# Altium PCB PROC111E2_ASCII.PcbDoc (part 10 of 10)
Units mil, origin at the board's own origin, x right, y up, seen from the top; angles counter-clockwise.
Board outline 7700 x 2300 mil, 6 copper layers (Top Layer, GND 1, SIG 1, SIG 2, GND 2, Bottom Layer), stack 78.711 mil thick; 767 components, 596 nets, 2755 pads, 1578 vias.
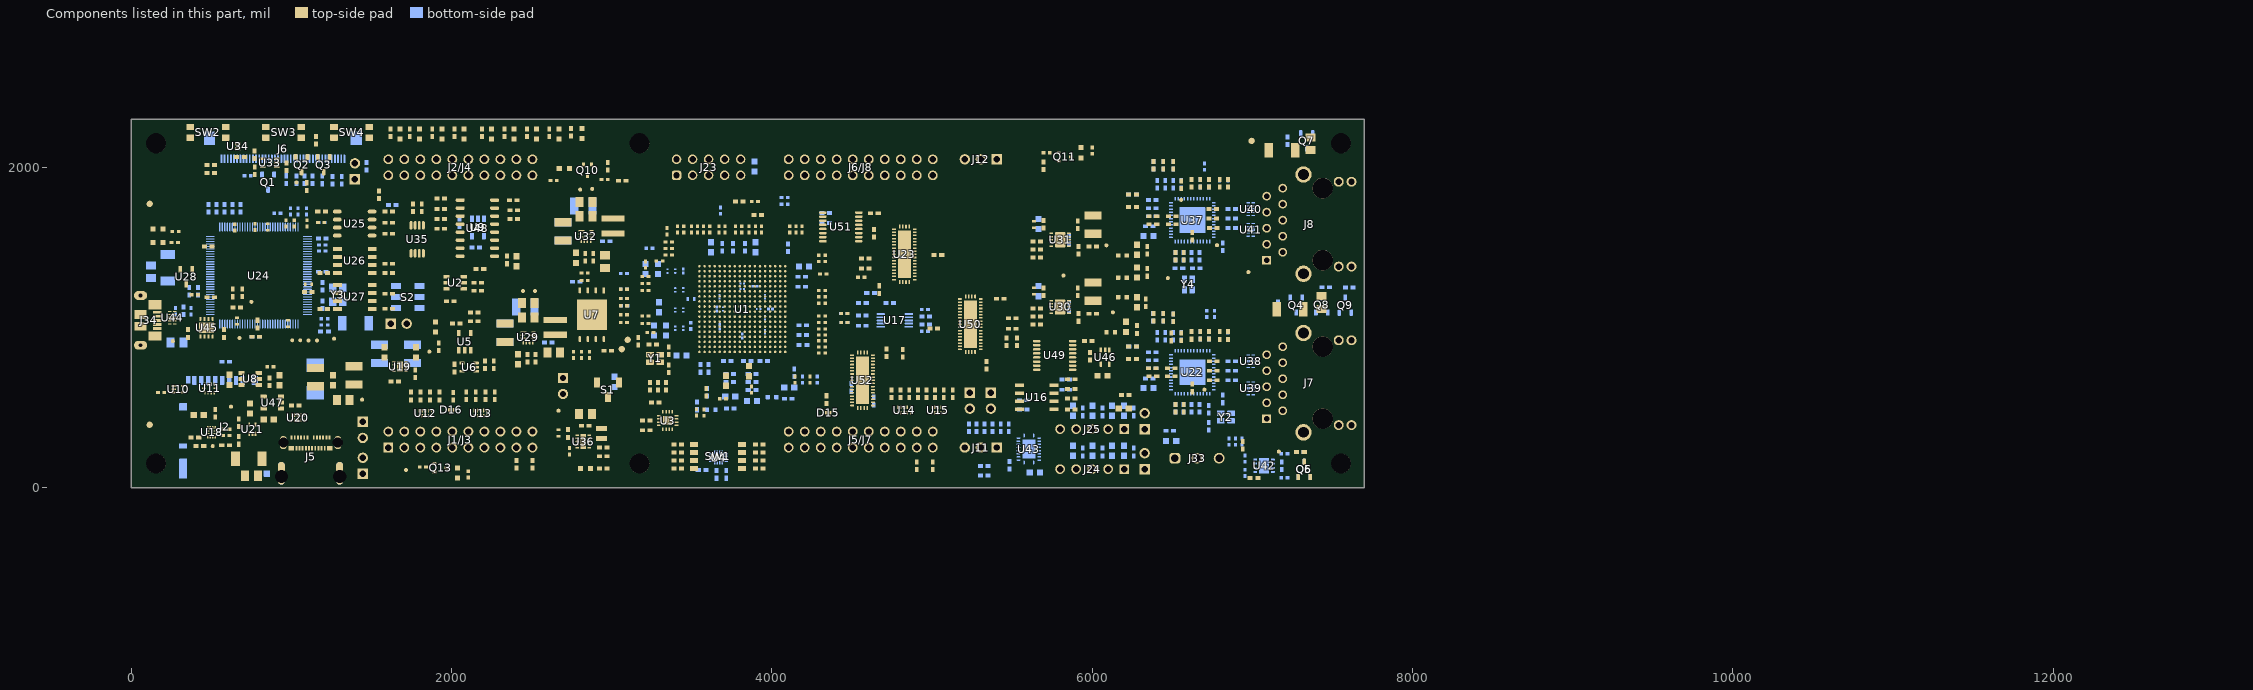
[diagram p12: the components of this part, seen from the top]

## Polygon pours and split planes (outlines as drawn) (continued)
VSYS_5V0 on SIG 2 "SIG 1-VSYS_5V0" (solid, remove dead copper, pour order 170): 5885,665 5925,625 6213.46,625 6258.42,580.04 6570.88,267.59 7230,267.55 7230,111.05 7183.95,65 2730.4,65 2569.6,199 1375,199 1375,530 1795,530 1795,919.76 1905,919.76 1905,1660 2821.22,1660 2821.22,1379.42 2494.42,1379.42 2450,1335 2450,722.59 2587.59,585 4815,585 4953.13,445 5268.44,445 5300,476.56 5300,660 5560,660 5560,1020.29 5485,1097.02 5485,1629.65 5515.35,1660 5560,1660 5885,1660
VDD_AM263_1V2 on SIG 2 "SIG 1-VDD_AM263_1V2" (solid, pour order 168): 3470.04,985 3505.4,1020.59 3625.87,1020.59 3647.25,999.21 3647.25,940.31 3615,908.06 3615,844.23 3985,844.23 3985,1070.33 4050,1070.33 4050,1155 3999.19,1155 3990,1164.19 3990,1223.39 3967.26,1246.14 3935.76,1246.14 3866.9,1315 3799.81,1315 3757.37,1272.56 3661.94,1272.56 3599.54,1334.96 2490,1334.96 2490,730.04 2706.09,730.04 2706.09,985 3106.05,985
VDD_ETH2_1V1_FILT on SIG 2 "SIG 2-VDD_ETH2_1V1_FILT" (solid, pour order 12): 6415.73,1433.78 6430.29,1448.34 6430.29,1494.41 6399.19,1525 6399.19,1671.12 6457.21,1671.12 6479.99,1648.34 6823.81,1648.34 6846.59,1671.12 6846.59,1759.22 6825.81,1780 6779.49,1780 6625.24,1934.26 6353.19,1934.26 6259.18,1840.24 6259.18,1473.95 6299.35,1433.78
VDD_ETH1_1V1_FILT on SIG 2 "SIG 2-VDD_ETH1_1V1_FILT" (solid, pour order 84): 6338.15,1339.91 6473.52,1339.91 6875.84,1339.91 6955,1260.74 6955,780.4 6863.7,689.1 6745,689.1 6713.73,720.37 6422.06,720.37 6422.06,937.27 6672.54,937.27 6798.75,937.27 6823.81,962.33 6823.81,1132.01 6751.99,1203.83 6338.15,1203.83
VSD_3V3 on SIG 2 "SIG 2-VSD_3V3" (solid, pour order 160): 510,810 631.97,810 631.97,567.83 220,567.83 220,751.21 510,751.21
SHIELD2 on SIG 2 "Top Layer-SHIELD2" (solid, pour order 211): 7250,329.68 7306.81,272.87 7412.87,272.87 7505,365 7505,416.54 7528.25,439.79 7650,439.79 7650,853.43 7535,853.43 7470,918.43 7470,1140 7250,1140
SHIELD3 on SIG 2 "Top Layer-SHIELD3" (solid, pour order 209): 7233.03,2130 7210,2106.97 7210,1963.31 7250,1923.31 7250,1277.87 7265,1262.87 7427.87,1262.87 7505,1340 7505,1406.54 7528.25,1429.79 7650,1429.79 7650,1843.43 7535,1843.43 7470,1908.43 7470,2130
VDDS_AM263_LDO_1V8 on SIG 2 "SIG 2-VDDS_AM263_LDO_1V8" (solid, pour order 14): 4144.81,1277.63 4076.04,1277.63 4061.86,1291.81 3993.63,1291.81 3993.63,1253.31 4057.7,1253.31 4091.01,1220 4140.09,1220 4154.85,1234.76 4154.85,1267.72 4143.94,1278.63
VDDS_AM263_LDO_1V8 on SIG 2 "SIG 2-VDDS_AM263_LDO_1V8 1" (solid, pour order 16): 3710,1305.1 3710,1416.01 3713.99,1420 3713.99,1460.97 3705,1469.95 3672.32,1469.95 3657.37,1455 3657.37,1415.8 3630.74,1389.17 3630.74,1315.74 3651.48,1295 3699.9,1295
GND on GND 1 "GND 1-GND" (solid, remove dead copper, pour order 200): 7504.17,284.98 7637.99,284.98 7670,317 7670,351.16 7657.89,363.27 7586.36,363.27 7569.87,379.77 7569.87,408.86 7560.02,418.7 7535,418.7 7510,393.7 7510,348.99 7406.01,245 7319,245 7315.63,244.67 7225,335.3 7225,1130 7250,1155 7476.02,1155 7588.78,1042.24 7637.99,1042.24 7637.99,1207.01 7582.13,1262.87 7250.44,1262.87 7225,1288.31 7225,2100 7270,2145 7350,2145 7385,2180 7385,2255 7365.49,2274.51 7225,2274.51 295,2275 295,1916.06 800,1916.06 800,1842.84 1445,1842.84 1445,820 498.97,820 498.97,729.88 85,729.88 85,25 7392.67,25 7415,47.33 7415,195.81
GND_XDS on GND 1 "SIG 1-VDD_XDS3V3" (solid, pour order 150): 280.17,1285.5 180,1185.32 180,1159.28 180,840 415,840 415,915 1355,915 1355,1745 695,1745 695,1830 60,1830 60,1365 280.17,1365
SHIELD1 on GND 1 "Top Layer-SHIELD1" (solid, pour order 148): 970,333.27 970,173.86 1268.3,173.86 1268.3,333.27 1335,333.27 1335,14.25 760,14.25 760,94.25 779.9,114.15 779.9,213.5 881.02,213.5 881.02,333.27
SHIELD3 on GND 1 "Top Layer-SHIELD3" (solid, pour order 235): 7233.03,2130 7210,2106.97 7210,1963.31 7250,1923.31 7250,1277.87 7265,1262.87 7427.87,1262.87 7505,1340 7505,1406.54 7528.25,1429.79 7650,1429.79 7650,1843.43 7535,1843.43 7470,1908.43 7470,2130
SHIELD2 on GND 1 "Top Layer-SHIELD2" (solid, pour order 203): 7250,329.68 7306.81,272.87 7412.87,272.87 7505,365 7505,416.54 7528.25,439.79 7650,439.79 7650,853.43 7535,853.43 7470,918.43 7470,1140 7250,1140
SHIELD4 on GND 1 "Bottom Layer-SHIELD4" (solid, pour order 158): 15,850 170,850 170,1189.07 270,1289.07 270,1333.26 15,1333.26
SHIELD1 on SIG 1 "Top Layer-SHIELD1" (solid, pour order 237): 970,333.27 970,173.86 1268.3,173.86 1268.3,333.27 1335,333.27 1335,14.25 760,14.25 760,94.25 779.9,114.15 779.9,213.5 881.02,213.5 881.02,333.27
VDDA_AM263_1V8_LDO on SIG 1 "SIG 1-VDDA_AM263_1V8_LDO" (solid, pour order 217): 3935.25,905 3975.05,905 3980.05,900 3980.05,890.84 4017.51,853.38 4017.51,767.97 4075,710.49 4123.94,710.49 4142.51,729.06 4142.51,829.91 3980.05,992.37 3980.05,1005.07 3935.25,1049.87 3632.52,1049.87 3632.52,905 3645,892.52 3645,656.74 3660,641.74 3690.3,641.74 3705,656.44 3705,801 3766.26,862.26 3766.26,905
VDDS_AM263_LDO_1V8 on SIG 1 "SIG 1-VDDS_AM263_LDO_1V8" (solid, pour order 221): 3573.07,908.07 3497,832 3497,780.82 3507.82,770 3576.79,770 3595,788.21 3595,870.25 3609.75,885 3609.75,898.64 3600.33,908.07
VDDA18_AM263_OSC_PLL on SIG 1 "SIG 1-VDDA18_AM263_OSC_PLL" (solid, remove dead copper, pour order 261): 3603.29,889.6 3603.29,921.41 3616.28,934.4 3630.57,934.4 3648.81,916.16 3648.81,874.6 3637.53,863.32 3637.53,744.95 3551.55,658.97 3545,658.97 3545,611.09 3525.17,591.26 3492.53,591.26 3470,613.79 3470,688.61 3531.39,750 3584.36,750 3611.97,777.61 3611.97,818.36 3603.23,827.1 3603.23,889.25
VDDS_AM263_LDO_1V8 on SIG 1 "SIG 1-VDDS_AM263_LDO_1V8 3" (solid, pour order 219): 3987.37,1248.64 3995,1241.01 4139.08,1241.01 4145.95,1247.88 4145.95,1264.05 4135,1275 4089.77,1275 4081.83,1267.05 4032.51,1267.05 4010.16,1289.4 3991.97,1289.4 3987.37,1284.8
VDDS_AM263_LDO_1V8 on SIG 1 "SIG 1-VDDS_AM263_LDO_1V8 2" (solid, pour order 225): 3990,977.32 3994.45,972.86 4160,972.86 4160,1020 4147.43,1032.57 4012.06,1032.57 3990,1010.51
VDDS_AM263_LDO_1V8 on SIG 1 "SIG 1-VDDS_AM263_LDO_1V8 1" (solid, pour order 227): 3674.62,1460 3664.99,1450.37 3664.99,1309.77 3681.25,1293.51 3709.82,1293.51 3725,1308.69 3725,1450 3715,1460
SHIELD2 on SIG 1 "Top Layer-SHIELD2" (solid, pour order 207): 7250,329.68 7306.81,272.87 7412.87,272.87 7505,365 7505,416.54 7528.25,439.79 7650,439.79 7650,853.43 7535,853.43 7470,918.43 7470,1140 7250,1140
SHIELD3 on SIG 1 "Top Layer-SHIELD3" (solid, pour order 205): 7233.03,2130 7210,2106.97 7210,1963.31 7250,1923.31 7250,1277.87 7265,1262.87 7427.87,1262.87 7505,1340 7505,1406.54 7528.25,1429.79 7650,1429.79 7650,1843.43 7535,1843.43 7470,1908.43 7470,2130
VSYS_3V3 on SIG 1 "SIG 1-VSYS_3V3" (solid, pour order 172): 3761.09,1315 3740.37,1315 3734.14,1308.77 3734.14,1280.46 3634.97,1280.46 3635.03,1198.85 3630.01,1193.83 3614.32,1193.83 3613.09,1192.6 3613.09,1169.94 3626.37,1156.66 3804.17,1156.66 3804.17,1287.1 3775.08,1316.2 3761.09,1316.2
GND on GND 2 "GND 1-GND" (solid, remove dead copper, pour order 186): 7225,305 7275.89,254.11 7418.11,254.11 7530.93,366.93 7644.23,366.93 7660,351.16 7660,305 7640,285 7500,285 7415,200 7415,47.33 7392.67,25 85,25 85,729.88 498.97,729.88 498.97,820 1445,820 1445,1842.84 800,1842.84 800,1916.06 295,1916.06 295,2275 7225,2275 7225,2274.51 7405.49,2274.51 7420,2260 7420,2079.71 7484.41,2015.29 7629.71,2015.29 7665,1980 7665,1940 7634.76,1909.76 7508.99,1909.76 7453.75,1965 7390.51,1965 7295.51,2060 7237.5,2060 7225,2047.5 7225,1288.31 7250.44,1262.87 7402.29,1262.87 7490,1350.57 7629.43,1350.57 7655,1325 7655,970.72 7624.87,940.59 7495.44,940.59 7476.02,960 7476.02,1137.8 7460,1155 7250,1155 7225,1130
GND_XDS on GND 2 "SIG 1-VDD_XDS3V3" (solid, pour order 188): 280.17,1285.5 180,1185.32 180,1159.28 180,840 415,840 415,915 1355,915 1355,1745 695,1745 695,1830 60,1830 60,1365 280.17,1365
SHIELD1 on GND 2 "Top Layer-SHIELD1" (solid, pour order 184): 970,333.27 970,173.86 1268.3,173.86 1268.3,333.27 1335,333.27 1335,14.25 760,14.25 760,94.25 779.9,114.15 779.9,213.5 881.02,213.5 881.02,333.27
SHIELD2 on GND 2 "Top Layer-SHIELD2" (solid, pour order 239): 7250,329.68 7306.81,272.87 7412.87,272.87 7505,365 7505,416.54 7528.25,439.79 7650,439.79 7650,853.43 7535,853.43 7470,918.43 7470,1140 7250,1140
SHIELD3 on GND 2 "Top Layer-SHIELD3" (solid, pour order 215): 7233.03,2130 7210,2106.97 7210,1963.31 7250,1923.31 7250,1277.87 7265,1262.87 7427.87,1262.87 7505,1340 7505,1406.54 7528.25,1429.79 7650,1429.79 7650,1843.43 7535,1843.43 7470,1908.43 7470,2130
SHIELD4 on GND 2 "Bottom Layer-SHIELD4" (solid, pour order 213): 15,850 170,850 170,1189.07 270,1289.07 270,1333.26 15,1333.26

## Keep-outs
Keep-Out Layer:
  lines w60: -145,800.57 460,800.57 460,865 1400,865 1400,1800 750,1800 750,1875 -125,1875
  text ".Layer_Name" at 577,-858.49 h60

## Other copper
Top Layer:
  text ".Layer_Name" at 577,-858.49 h60
Bottom Layer:
  text ".Layer_Name" at 577,-858.49 h60

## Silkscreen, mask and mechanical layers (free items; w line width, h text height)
Top Overlay:
  lines w6: 1523,2149 1554.5,2117.5 1588,2151 1588,2275 1523,2275 1523,2149 ; 1535.67,460.5 1535.67,586.5 1600.67,586.5 1600.67,462.5 1567.17,429 1535.67,460.5 ; 1638.5,460.5 1638.5,586.5 1703.5,586.5 1703.5,462.5 1670,429 1638.5,460.5 ; 3385.35,1871.38 3419.92,1871.38 3420,1871.46 3430,1871.46 3407.72,1893.74 3385.35,1871.38 ; 4065,2144 4065,2270 4150,2270 4150,2146 4106.5,2102.5 4065,2144 ; 6180.35,34.92 6202.72,57.28 6225,35 6215,35 6214.92,34.92 6180.35,34.92 ; 6180.35,281.78 6202.72,304.14 6225,281.86 6215,281.86 6214.92,281.78 6180.35,281.78
  text "SW4" at 1131.5,2246.76 h30
  text "SW3" at 700,2230 h30
  text "U34" at 646.08,2175 h30
  text "GND" at 1577,2155 h40 r90
  text "ASSY" at 4165,2155 h108.27
  text "GND" at 4129,2150 h40 r90
  text "FSI" at 3480,2146.38 h100
  text "SL#" at 6095,2140 h108.27
  text "3V3" at 5455.61,2120 h50 r90
  text "GND" at 5315,2112.06 h50 r90
  text "GND" at 5217.15,2110 h50 r90
  text "Q3" at 1206.61,2107.6 h30
  text "Q2" at 1048.5,2102.06 h30
  text "RESETn" at 835,2100 h50
  text "INT1" at 1419.88,2100 h50
  text "D4" at 2783.82,2100 h30
  text "D7" at 2642.5,2099 h30
  text "D14" at 1660,2095 h30
  text "D13" at 1770,2095 h30
  text "D12" at 1910.31,2095 h30
  text "D11" at 2050.31,2095 h30
  text "D10" at 2221.73,2095 h30
  text "D9" at 2370,2095 h30
  text "D8" at 2510,2095 h30
  text "SW2" at 290,2087.06 h30
  text "PORZ" at 430.11,2068.5 h50
  text "Q10" at 2828,2053.57 h30
  text "DS1" at 2680.5,2039.5 h30
  text "J12" at 5245.35,1944.87 h30
  text "U33" at 827.55,1927.02 h30
  text "J8" at 6933.56,1910 h30
  text "ERROR" at 2684,1905.5 h30
  text "J1" at 1286,1889.5 h30
  text "J23" at 3588.88,1846.72 h30
  text "U48" at 2128.41,1842.03 h30
  text "U31" at 5765,1666.3 h30
  text "L3" at 3121.51,1617.46 h30
  text "U25" at 1145,1571.55 h30
  text "PROC111E2" at 4971.79,1550 h108.27
  text "U32" at 2933.86,1505 h30
  text "U35" at 1871.68,1490.54 h30
  text "D3" at 170,1456.26 h30
  text "U26" at 1145,1443.54 h30
  text "U28" at 311.68,1422.49 h30
  text "ICSSM_MII0" at 6983.84,1395.24 h60 r90
  text "CPSW RGMII2/" at 6918.84,1391.97 h60 r90
  text "XDS110" at 40,1321.39 h50
  text "UART0" at 50,1271.09 h50
  text "U2" at 1864.39,1265 h30
  text "U7" at 2710,1259.59 h30
  text "U30" at 5766.51,1242.07 h30
  text "U23" at 4787.7,1205.09 h30
  text "J34" at 208.94,1201.07 h30
  text "U27" at 1151.79,1153.83 h30
  text "L2" at 2655,1125 h30
  text "U1" at 3440,1115 h30
  text "U44" at 306.68,1089.61 h30
  text "U45" at 470.31,1089.61 h30
  text "J17" at 1751.08,1090 h30 r90
  text "D2" at 1883.5,1084.15 h30
  text "ADC_VREF" at 1825,975 h30 r90
  text "TP26" at 1280.17,961.01 h30 r90
  text "U49" at 5736.51,947.43 h30
  text "U29" at 2420,921.24 h25 r90
  text "U5" at 2187.34,891.81 h30
  text "J7" at 6938.53,860 h30
  text "U19" at 1642.67,828.66 h30
  text "Y1" at 3141.94,777.58 h30
  text "U8" at 712.47,762.13 h30
  text "U11" at 452.28,685 h30
  text "3V3" at 5205,675 h50
  text "U10" at 245,670.83 h30
  text "5V0" at 5347.64,663.97 h50
  text "U6" at 2087.02,662 h30
  text "J18" at 2550,613.19 h30
  text "U3" at 3379.6,519 h30
  text "5V" at 1588.17,486.65 h40 r90
  text "DAC_VREF" at 2954.92,485 h50
  text "J10" at 1422.5,476.5 h30
  text "GND" at 1692.5,466.5 h40 r90
  text "J16" at 6391.51,461.21 h30
  text "U13" at 2260.8,448.82 h30
  text "EQEP2" at 5960,443.25 h50
  text "U15" at 4996.51,411.21 h30
  text "U14" at 4776.51,404.83 h30
  text "U12" at 1735,397.64 h30
  text "J13" at 5191.02,394.66 h30
  text "J14" at 5326.51,389.83 h30
  text "U18" at 352.91,370.89 h30
  text "ICSSM_MII1" at 7000,363.27 h60 r90
  text "CPSW RGMII1/" at 6935,360 h60 r90
  text "J33" at 6530,353 h30
  text "PWR IN" at 964,344.96 h80
  text "SW1" at 3611.51,344.83 h30
  text "MCAN0" at 6685,344.96 h30
  text "J5" at 885.5,341 h30
  text "J25" at 5645,330 h30
  text "J11" at 5249.61,325.69 h30
  text "U21" at 711.51,271.69 h30
  text "EQEP0" at 5930,210 h50
  text "J15" at 6176.51,200.93 h30
  text "D5" at 2015,181.5 h30
  text "U36" at 2781.51,169.83 h30
  text "J24" at 5646.51,114.83 h30
  text "5V0" at 5428.52,110 h50 r90
  text "CANA_N" at 6430,110 h30 r90
  text "J9" at 1375.17,109.01 h30 r90
  text "GND" at 5222.77,93.16 h50 r90
  text "GND" at 5324.39,90 h50 r90
  text "Q5" at 7160,80 h30
  text "uSD" at 410,72.38 h108.27
  text "HIGH" at 3364,43.5 h30
  text "LOW" at 3885,43.5 h30
  text "D6" at 2805,41.85 h30
  text "CANA_P" at 6910,39.9 h30 r90
  text "BOOTMODE" at 3543,17.5 h30
  text ".Layer_Name" at 577,-858.49 h60
Bottom Overlay:
  drawing of 4372 lines, arcs and shapes, not listed
  text "J6" at 415,2065 h30
  text "Q7" at 7336.65,2043.21 h30
  text "Q1" at 870,1985.02 h30
  text "TEST AUTOMATION HEADER" at 664.53,1934.26 h30
  text "U40" at 7010,1823.21 h30
  text "www.ti.com/launchpad" at 4965,1783.45 h30 r90
  text "Development Kit" at 5535,1685.95 h30 r90
  text "U9" at 2315,1604.88 h30
  text "LP-AM263" at 5455,1583.95 h30 r90
  text "U41" at 7008.56,1500.78 h30
  text "U37" at 6465,1486.82 h30
  text "U24" at 430.32,1411.43 h30
  text "VREF Select" at 1875.39,1335.55 h30
  text "Y3" at 1330,1321.12 h30
  text "4" at 1596.57,1247.62 h30
  text "1" at 1864.39,1245 h30
  text "C234" at 1465,1128.43 h30 r270
  text "6" at 1602.07,1104.9 h30
  text "3" at 1875.39,1104.9 h30
  text "Q4" at 7265,1027.71 h30
  text "Q8" at 7467.49,1021.98 h30
  text "Q9" at 7595,1011.5 h30
  text "U17" at 4800,928.21 h30
  text "U38" at 7017.5,871.84 h30
  text "D1" at 1295,655 h30
  text "GND" at 4220,535.5 h36 r90
  text "U22" at 6460.13,535 h30
  text "U39" at 7010,510.96 h30
  text "5V" at 4113.67,509.48 h40 r90
  text "J2" at 935,495.5 h30
  text "Y2" at 6960,429.59 h30
  text "U43" at 5636.86,375 h30
  text "U42" at 7105,230 h30
  text "U4" at 3795,213.21 h30
  text "Q6" at 7420,196.5 h30
  text ".Layer_Name" at 577,-858.49 h60
Top Paste:
  text ".Layer_Name" at 577,-858.49 h60
Bottom Paste:
  text ".Layer_Name" at 577,-858.49 h60
Top Solder:
  text ".Layer_Name" at 577,-858.49 h60
  text ".Layer_Name" at 577,-858.49 h60
Bottom Solder:
  text ".Layer_Name" at 577,-858.49 h60
Drill Guide:
  text ".Layer_Name" at 577,-858.49 h60
M1 Board Outline:
  the board outline again, w10
  text ".Layer_Name" at 577,-858.49 h60
M2 Board Dimensions:
  rectangle: 0,-275 125,-150
  rectangle: 125,-400 500,-275
  lines w7: 0,-275 1000,-275 ; 125,-400 125,-150 ; 250,-400 250,-150 ; 500,-400 500,-150 ; 750,-400 750,-150 ; 0,-400 1000,-400 1000,-150 0,-150 0,-400
  text ".Layer_Name" at 577,-858.49 h60
M3 3D STEP Top:
  text ".Layer_Name" at 577,-858.49 h60
M4 3D STEP Bottom:
  text ".Layer_Name" at 577,-858.49 h60
M5 Assembly Top:
  lines w10: -292,-930.17 6308,-930.17 ; -292,-726.83 6310,-726.83 ; -292,-523.5 -292,-1133.5 3713,-1133.5 6310,-1133.5 6310,-523.5 -291.5,-523.5 -291.5,-1133.5 1284,-1133.5 ; 2173,-1133.5 2173,-523.5 ; 3440,-726.83 3440,-523.5 ; 4280,-726.83 4280,-523.5 ; 4902,-1140 4902,-937.17
  text "COMPONENTS MARKED 'DNP' SHOULD NOT BE POPULATED." at 1153.5,-318.5 h60
  text "ASSEMBLY VARIANT:" at 1153,-434 h60
  text ".VariantName" at 2189,-434 h60
  text "PCB VIEWED FROM TOP SIDE" at -228.5,-655.67 h60
  text "BOARD #:" at 2248,-655.67 h60
  text ".PRJ_Number" at 2793.5,-655.67 h60
  text "REV:" at 3638,-655.67 h60
  text ".PCB_Rev" at 3929.5,-655.67 h60
  text "SVN REV:" at 4476,-655.67 h60
  text ".VersionControl_RevNumber" at 4982,-655.67 h60
  text "TID #:" at 2248,-859 h60
  text ".TID" at 2793.5,-859 h60
  text "PLOT NAME =" at -228.5,-1064.34 h60
  text ".plot_File_Name" at 577,-1064.34 h60
  text "GENERATED    :" at 2250,-1064.34 h60
  text ".Print_Date" at 3119.5,-1064.34 h60
  text ".Print_Time" at 3848.5,-1064.34 h60
  text "TEXAS INSTRUMENTS" at 5113,-1064.34 h60
M6 Assembly Bottom:
  lines w10: -292.5,-727.33 6309.5,-727.33 ; -290.5,-930.67 6309.5,-930.67 ; 1115.5,-1140.5 1115.5,-937.67 ; 1737.5,-727.33 1737.5,-524 ; 2577.5,-727.33 2577.5,-524 ; 3844.5,-1134 3844.5,-524 ; 4733.5,-1134 6309,-1134 6309,-524 -292.5,-524 -292.5,-1134 2304.5,-1134 6309.5,-1134 6309.5,-524
  text "COMPONENTS MARKED 'DNP' SHOULD NOT BE POPULATED." at 6102,-318 h60
  text ".VariantName" at 5058,-434 h60
  text "ASSEMBLY VARIANT:" at 6097,-434 h60
  text ".VersionControl_RevNumber" at 1035.5,-656.17 h60
  text "SVN REV:" at 1541.5,-656.17 h60
  text ".PCB_Rev" at 2088,-656.17 h60
  text "REV:" at 2379.5,-656.17 h60
  text ".PRJ_Number" at 3224,-656.17 h60
  text "BOARD #:" at 3769.5,-656.17 h60
  text "PCB VIEWED FROM BOTTOM SIDE" at 6246,-656.17 h60
  text ".TID" at 3224,-859.5 h60
  text "TID #:" at 3769.5,-859.5 h60
  text "TEXAS INSTRUMENTS" at 904.5,-1064.84 h60
  text ".Print_Time" at 2169,-1064.84 h60
  text ".Print_Date" at 2898,-1064.84 h60
  text "GENERATED    :" at 3767.5,-1064.84 h60
  text ".plot_File_Name" at 5440.5,-1064.84 h60
  text "PLOT NAME =" at 6246,-1064.84 h60
M9 Title Sheet:
  lines w10: -491.5,1041.5 -291.5,1041.5 ; -491.5,3416.5 -291.5,3416.5 ; -491.5,5791.5 -291.5,5791.5 ; 2008.5,-1333.5 2008.5,-1133.5 ; 2008.5,7966.5 2008.5,8166.5 ; 4508.5,-1333.5 4508.5,-1133.5 ; 4508.5,7966.5 4508.5,8166.5 ; 6321,-1133.5 6321,-523.5 11303.5,-523.5 ; 7008.5,-1333.5 7008.5,-1133.5 ; 7008.5,7966.5 7008.5,8166.5 ; 9508.5,-1333.5 9508.5,-1133.5 ; 9508.5,7966.5 9508.5,8166.5 ; 11303.5,-1133.5 11303.5,-523.5 ; 11303.5,-823.5 14303.5,-823.5 ; 11303.5,-223.5 14303.5,-223.5 ; 11304.5,370.5 14304.5,370.5 ; 12008.5,-1333.5 12008.5,-1133.5 ; 12008.5,7966.5 12008.5,8166.5 ; 12808.5,-1123.5 12808.5,-523.5 ; 14303.5,-523.5 11303.5,-523.5 ; 14303.5,76.5 11303.5,76.5 ; 14308.5,66.5 14308.5,-1133.5 ; 14308.5,871 11304.5,871 11303.5,871 11303.5,370.5 11303.5,76.5 ; 14308.5,1041.5 14508.5,1041.5 ; 14308.5,3416.5 14508.5,3416.5 ; 14308.5,5791.5 14508.5,5791.5 ; 11303.5,-523.5 11303.5,76.5 ; 14308.5,-1133.5 14308.5,7966.5 -291.5,7966.5 -291.5,-1133.5 14308.5,-1133.5 ; -491.5,-1333.5 -491.5,8166.5 14508.5,8166.5 14508.5,-1333.5 -491.5,-1333.5
  text "1" at 739.84,8036.5 h70
  text "2" at 3235.5,8036.5 h70
  text "3" at 5724.84,8036.5 h70
  text "4" at 8194.51,8036.5 h70
  text "5" at 10693.5,8036.5 h70
  text "6" at 13235.5,8036.5 h70
  text "A" at -416.5,6893.5 h70
  text "A" at 14383.5,6893.5 h70
  text "B" at -416.5,4513.5 h70
  text "B" at 14383.5,4513.5 h70
  text "C" at -416.5,2138.5 h70
  text "C" at 14383.5,2138.5 h70
  text "PROJECT TITLE:" at 11343.5,277.5 h45
  text ".PRJ_Title" at 11393.5,144.17 h70
  text "DESIGNED FOR:" at 11343.5,-23.5 h45
  text ".PRJ_Customer" at 11393.5,-163.5 h70
  text "D" at -416.5,-231.5 h70
  text "D" at 14383.5,-231.5 h70
  text "FILE NAME:" at 11343.5,-323.5 h45
  text ".PCB_File_Name_No_Path" at 11393.5,-443.5 h70
  text "Texas Instruments (TI) and/or its licensors do not warrant the accuracy or completeness of this specification" at 6374,-605.34 h45
  text "ENGINEER:" at 11343.5,-613.5 h45
  text "LAYOUT BY:" at 12848.5,-613.5 h45
  text "or any information contained therein. TI and/or its licensors do not warrant that this design will meet" at 6329.01,-718 h45
  text ".PRJ_Engineer" at 11393.5,-768.49 h70
  text ".PCB_Layout" at 12899,-768.49 h70
  text "the specifications, will be suitable for your application or fit for any particular purpose, or will operate in" at 6329.01,-830.67 h45
  text ".Layer_Name" at 577,-858.49 h60
  text "ALTIUM DESIGNER VERSION:" at 12848.5,-923.5 h45
  text "an implementation. TI and/or its licensors do not warrant that the design is production worthy. You should" at 6329.01,-943.33 h45
  text "completely validate and test your design implementation to confirm the system functionality for your application." at 6374,-1056 h45
  text ".print_Scale" at 11393.5,-1056.83 h70
  text ".Application_BuildNumber" at 12899,-1056.83 h70
  text "1" at 739.84,-1263.5 h70
  text "2" at 3235.5,-1263.5 h70
  text "3" at 5724.84,-1263.5 h70
  text "4" at 8231.51,-1263.5 h70
  text "5" at 10730.5,-1263.5 h70
  text "6" at 13235.5,-1263.5 h70
M10 Fab Notes:
  drawing of 189 lines, arcs and shapes, not listed
  text "DESIGN INFORMATION" at 12382.02,6356.17 h60
  text "MIN. TRACK WIDTH:" at 11737.46,6224.05 h60
  text "4" at 12833.7,6224.05 h60
  text "MIL" at 12988.46,6224.05 h60
  text "MIN. CLEARANCE:" at 11737.46,6099.92 h60
  text "4" at 12833.7,6099.92 h60
  text "MIL" at 12988.46,6099.92 h60
  text "MIN. VIA PAD SIZE:" at 11737.46,5975.8 h60
  text "18" at 12803.71,5975.8 h60
  text "MIL" at 12988.46,5975.8 h60
  text "0.05mm (2MIL)" at 12432.46,5845.9 h60
  text "MINIMUM ANNULAR RING" at 11408.23,5837.67 h60
  text "EXTERNAL" at 13140.46,5837.67 h60
  text "PER" at 11608.23,5727.55 h60
  text "IPC-D-275 CLASS 2 LEVEL C" at 11828.23,5727.54 h60
  text "MIL, HOLES" at 13316.46,5627.07 h60
  text "+/-" at 12924,5618.48 h60
  text "+/-" at 13778,5618.48 h60
  text "REGISTRATION TOLERANCES:" at 11408.23,5617.42 h60
  text "METAL" at 12608,5617.42 h60
  text "5" at 13184.2,5617.42 h60
  text "3" at 14017.2,5617.42 h60
  text "MIL" at 14133.46,5617.42 h60
  text "HOLE SIZE TOLERANCE (UNLESS OTHERWISE SPECIFIED):" at 11408.23,5519.1 h60
  text "+/-" at 13778,5516.23 h60
  text "3" at 14017.2,5515.17 h60
  text "MIL" at 14133.46,5515.17 h60
  text "MATERIAL:" at 11333.46,5377.52 h60
  text "FR-4 High Tg" at 12319.9,5249 h60
  text "X" at 12175.46,5241.01 h60
  text "FR-408" at 11754.46,5236.49 h60
  text "OTHER" at 13242.46,5236.49 h60
  text "62 MIL (1.6mm) +/-10%" at 12074.56,5093.46 h60
  text "X" at 11954.46,5091.01 h60
  text "THICKNESS:" at 11408.23,5085.24 h60
  text "OTHER" at 13359.46,5085.24 h60
  text "TOLERANCE:" at 11408.23,4946.92 h60
  text "X" at 12256.46,4946.92 h60
  text "ANSI IPC-6012 TYPE 3 CLASS 2" at 12434.48,4946.92 h60
  text "OTHER +/-" at 12434.46,4802.73 h60
  text "BOW & TWIST:" at 11408.23,4657.54 h60
  text "X" at 12256.46,4657.54 h60
  text "ANSI IPC-6012 TYPE 3 CLASS 2" at 12434.48,4657.54 h60
  text "OTHER +/-" at 12434.46,4510.85 h60
  text "DRILLING:" at 11333.46,4380.23 h60
  text "NC_DRILL FILES" at 13094.46,4275.04 h60
  text "REFERENCE:" at 11408.23,4271.1 h60
  text "X" at 12065.46,4271.01 h60
  text "AS SHOWN" at 12243.46,4271.1 h60
  text "X" at 12966.46,4271.1 h60
  text "OTHER" at 13392.46,4128.85 h60
  text "PTH COPPER THICKNESS:" at 11407.91,4125.32 h60
  text "X" at 12547.14,4125.32 h60
  text "20-30 um" at 12675.14,4125.32 h60
  text "BOARD FINISH:" at 11333.46,3977.73 h60
  text "SILKSCREEN:" at 11488.68,3867.6 h60
  text "X" at 12446.46,3867.6 h60
  text "TOP" at 12563.46,3867.6 h60
  text "X" at 12956.46,3867.6 h60
  text "BOTTOM" at 13074.46,3867.6 h60
  text "SILKSCREEN COLOR:" at 11488.68,3712.41 h60
  text "X" at 12445.46,3712.41 h60
  text "WHITE" at 12563.46,3712.41 h60
  text "OTHER" at 13074.46,3712.41 h60
  text "GREEN" at 12694.46,3568.96 h60
  text "X" at 13168.46,3568.96 h60
  text "OTHER" at 13312.46,3568.96 h60
  text "RED" at 13671.46,3568.96 h60
  text "SOLDER RESIST COLOR:" at 11488.68,3562.1 h60
  text "X" at 12576.46,3414.71 h60
  text "MATTE" at 12694.46,3414.71 h60
  text "SEMI-GLOSS" at 13312,3414.07 h60
  text "IMMERSION GOLD (ENIG)" at 12394.46,3241.94 h60
  text "ENEPIG" at 13732,3234.72 h60
  text "SURFACE FINISH:" at 11333.46,3233.72 h60
  text "X" at 12216.46,3233.72 h60
  text "IMM. TIN/SILVER OR EQUIV" at 11663,3096.4 h60
  text "OTHER" at 13094.46,3092.47 h60
  text "ARRAY/PANEL:" at 11333.46,2937.09 h60
  text "CUT AND TRIM PER M1 BOARD OUTLINE" at 12394.46,2928.87 h60
  text "N.C. ROUTE" at 12394.46,2792.9 h60
  text "X" at 13082.46,2792.9 h60
  text "V. SCORE" at 13260.46,2792.9 h60
  text "CERTIFICATION:" at 11333.46,2663.77 h60
  text "MATERIALS AND WORKMANSHIP FOR ALL PCBS" at 12058.46,2663.77 h60
  text "TO MEET OR EXCEED THE REQUIREMENTS OF:" at 12058.46,2569.71 h60
  text "X" at 11695.97,2441.08 h60
  text "ANSI IPC-A-600F CLASS ->" at 11823.96,2441.08 h60
  text "X" at 13471.97,2441.08 h60
  text "2" at 13581.96,2441.08 h60
  text "1" at 13266.96,2439.58 h60
  text "3" at 13935.96,2439.58 h60
  text "X" at 12507.97,2293.39 h60
  text "RoHS" at 12635.96,2293.39 h60
  text "OTHER" at 13280.36,2293.39 h60
  text "PER ORDER" at 13677.42,2293.39 h60
  text "ALL BOARDS MUST MEET OR EXCEED UL94-V0 REQUIREMENTS." at 11361,2139.57 h60
  text "PCB MUST BEAR THE UL94V-0 UL REGISTERED MATERIAL ID NUMBER" at 11361,2023.5 h60
  text "ADDITIONAL REQUIREMENTS:" at 11333.46,1854.08 h60
  text "MICROSECTION:" at 11408.23,1746.95 h60
  text "YES" at 12313.96,1746.95 h60
  text "REQUIRED" at 13175.46,1602.62 h60
  text "BARE BOARD ELEC. TEST:" at 11408.23,1599.76 h60
  text "NONE" at 12713.96,1599.76 h60
  text "X" at 13057.46,1599.76 h60
  text "PER ORDER" at 13767.46,1599.76 h60
  text "XX MIL VIAS REQUIRE NON-CONDUCTIVE FILL AND PLANARIZE" at 11576.38,1394.82 h59
  text "XX MIL VIAS REQUIRE CONDUCTIVE FILL AND PLANARIZE" at 11584.38,1290.84 h60
  text "OUTER XX MIL TRACES REQUIRE 50 OHM SINGLE-ENDED IMPEDANCE" at 11583.39,1127.46 h58
  text "LAYER 2 & 3 (INNER LAYERS) XX MIL WIDE, XX MIL SPACE / TRACES REQUIRE 100 OHM DIFFERENTIAL IMPEDANCE" at 11575.39,891.74 h60
  text ".Layer_Name" at 577,-858.49 h60
M11 Gerber Information:
  lines w10: -292,-930.17 6308,-930.17 ; -292,-726.83 6310,-726.83 ; -292,-523.5 -292,-1133.5 3713,-1133.5 6310,-1133.5 6310,-523.5 -291.5,-523.5 -291.5,-1133.5 1284,-1133.5 ; 2173,-1133.5 2173,-523.5 ; 3440,-726.83 3440,-523.5 ; 4280,-726.83 4280,-523.5 ; 4902,-1140 4902,-937.17
  text "ALL ARTWORK VIEWED FROM TOP SIDE" at -228.5,-655.67 h60
  text "BOARD #:" at 2248,-655.67 h60
  text ".PRJ_Number" at 2793.5,-655.67 h60
  text "REV:" at 3638,-655.67 h60
  text ".PCB_Rev" at 3929.5,-655.67 h60
  text "SVN REV:" at 4476,-655.67 h60
  text ".VersionControl_RevNumber" at 4982,-655.67 h60
  text "LAYER NAME =" at -228.5,-858.49 h60
  text "TID #:" at 2248,-859 h60
  text ".TID" at 2793.5,-859 h60
  text "PLOT NAME =" at -228.5,-1064.34 h60
  text ".plot_File_Name" at 577,-1064.34 h60
  text "GENERATED    :" at 2250,-1064.34 h60
  text ".Print_Date" at 3119.5,-1064.34 h60
  text ".Print_Time" at 3848.5,-1064.34 h60
  text "TEXAS INSTRUMENTS" at 5113,-1064.34 h60
M12 Stackup:
  drawing of 399 lines, arcs and shapes, not listed
  text "Layer" at 60.09,6725 h60
  text "Name" at 470,6725 h60
  text "Material" at 1399.74,6725 h60
  text "Thickness" at 2259.51,6725 h60
  text "Constant" at 2909.35,6725 h60
  text "Board Layer Stack" at 3479.21,6725 h60
  text "Top Overlay" at 470,6605 h60
  text "Top Solder" at 470,6485 h60
  text "Solder Resist" at 1399.74,6485 h60
  text "0.40mil" at 2259.51,6485 h60
  text "3.5" at 2909.35,6485 h60
  text "1" at 60.09,6365 h60
  text "Top Layer" at 470,6365 h60
  text "1.40mil" at 2259.51,6365 h60
  text "Dielectric 1" at 470,6245 h60
  text "PP-006" at 1399.74,6245 h60
  text "2.80mil" at 2259.51,6245 h60
  text "4.1" at 2909.35,6245 h60
  text "2" at 60.09,6125 h60
  text "GND 1" at 470,6125 h60
  text "1.38mil" at 2259.51,6125 h60
  text "Dielectric 3" at 470,6005 h60
  text "PP-006" at 1399.74,6005 h60
  text "2.80mil" at 2259.51,6005 h60
  text "4.1" at 2909.35,6005 h60
  text "3" at 60.09,5885 h60
  text "SIG 1" at 470,5885 h60
  text "1.38mil" at 2259.51,5885 h60
  text "Dielectric1" at 470,5765 h60
  text "FR-4 High Tg" at 1399.74,5765 h60
  text "59.20mil" at 2259.51,5765 h60
  text "4.8" at 2909.35,5765 h60
  text "4" at 60.09,5645 h60
  text "SIG 2" at 470,5645 h60
  text "1.38mil" at 2259.51,5645 h60
  text "Dielectric 4" at 470,5525 h60
  text "PP-006" at 1399.74,5525 h60
  text "2.80mil" at 2259.51,5525 h60
  text "4.1" at 2909.35,5525 h60
  text "5" at 60.09,5405 h60
  text "GND 2" at 470,5405 h60
  text "1.38mil" at 2259.51,5405 h60
  text "Dielectric 2" at 470,5285 h60
  text "PP-006" at 1399.74,5285 h60
  text "2.80mil" at 2259.51,5285 h60
  text "4.1" at 2909.35,5285 h60
  text "6" at 60.09,5165 h60
  text "Bottom Layer" at 470,5165 h60
  text "1.40mil" at 2259.51,5165 h60
  text "Bottom Solder" at 470,5045 h60
  text "Solder Resist" at 1399.74,5045 h60
  text "0.40mil" at 2259.51,5045 h60
  text "3.5" at 2909.35,5045 h60
  text "Bottom Overlay" at 470,4925 h60
  text ".Layer_Name" at 577,-858.49 h60
M13 Component Bodies Top:
  text ".Layer_Name" at 577,-858.49 h60
M14 Component Bodies Bottom:
  text ".Layer_Name" at 577,-858.49 h60
M15 Courtyards Top:
  text ".Layer_Name" at 577,-858.49 h60
M16 Courtyards Bottom:
  text ".Layer_Name" at 577,-858.49 h60
Drill Drawing:
  drawing of 168 lines, arcs and shapes, not listed
  text "Symbol" at 4874.51,6728.08 h72
  text "Quantity" at 5175.11,6728.08 h72
  text "Finished Hole Size" at 5507.12,6728.08 h72
  text "Plated" at 6143.67,6728.08 h72
  text "Hole Type" at 6402.78,6728.08 h72
  text "Drill Layer Pair" at 6777.93,6728.08 h72
  text "Hole Tolerance" at 7501.32,6728.08 h72
  text "6" at 5175.11,6603.9 h60
  text "126.00mil (3.200mm)" at 5507.12,6603.9 h60
  text "NPTH" at 6143.67,6603.9 h60
  text "Round" at 6402.78,6603.9 h60
  text "Top Layer - Bottom Layer" at 6777.93,6603.9 h60
  text "+/-3.00mil" at 7501.32,6603.9 h60
  text "4" at 5175.11,6479.72 h60
  text "127.95mil (3.250mm)" at 5507.12,6479.72 h60
  text "NPTH" at 6143.67,6479.72 h60
  text "Round" at 6402.78,6479.72 h60
  text "Top Layer - Bottom Layer" at 6777.93,6479.72 h60
  text "104" at 5175.11,6355.55 h60
  text "7.87mil (0.200mm)" at 5507.12,6355.55 h60
  text "PTH" at 6143.67,6355.55 h60
  text "Round" at 6402.78,6355.55 h60
  text "Top Layer - Bottom Layer" at 6777.93,6355.55 h60
  text "1474" at 5175.11,6231.37 h60
  text "8.00mil (0.203mm)" at 5507.12,6231.37 h60
  text "PTH" at 6143.67,6231.37 h60
  text "Round" at 6402.78,6231.37 h60
  text "Top Layer - Bottom Layer" at 6777.93,6231.37 h60
  text "20" at 5175.11,6107.2 h60
  text "35.43mil (0.900mm)" at 5507.12,6107.2 h60
  text "PTH" at 6143.67,6107.2 h60
  text "Round" at 6402.78,6107.2 h60
  text "Top Layer - Bottom Layer" at 6777.93,6107.2 h60
  text "10" at 5175.11,5983.02 h60
  text "39.37mil (1.000mm)" at 5507.12,5983.02 h60
  text "PTH" at 6143.67,5983.02 h60
  text "Round" at 6402.78,5983.02 h60
  text "Top Layer - Bottom Layer" at 6777.93,5983.02 h60
  text "34" at 5175.11,5858.84 h60
  text "40.00mil (1.016mm)" at 5507.12,5858.84 h60
  text "PTH" at 6143.67,5858.84 h60
  text "Round" at 6402.78,5858.84 h60
  text "Top Layer - Bottom Layer" at 6777.93,5858.84 h60
  text "88" at 5175.11,5734.67 h60
  text "40.16mil (1.020mm)" at 5507.12,5734.67 h60
  text "PTH" at 6143.67,5734.67 h60
  text "Round" at 6402.78,5734.67 h60
  text "Top Layer - Bottom Layer" at 6777.93,5734.67 h60
  text "3" at 5175.11,5610.49 h60
  text "47.24mil (1.200mm)" at 5507.12,5610.49 h60
  text "PTH" at 6143.67,5610.49 h60
  text "Round" at 6402.78,5610.49 h60
  text "Top Layer - Bottom Layer" at 6777.93,5610.49 h60
  text "4" at 5175.11,5486.32 h60
  text "66.93mil (1.700mm)" at 5507.12,5486.32 h60
  text "PTH" at 6143.67,5486.32 h60
  text "Round" at 6402.78,5486.32 h60
  text "Top Layer - Bottom Layer" at 6777.93,5486.32 h60
  text "2" at 5175.11,5362.14 h60
  text "23.62mil (0.600mm)" at 5507.12,5362.14 h60
  text "PTH" at 6143.67,5362.14 h60
  text "Slot" at 6402.78,5362.14 h60
  text "Top Layer - Bottom Layer" at 6777.93,5362.14 h60
  text "2" at 5175.11,5237.96 h60
  text "62.99mil (1.600mm)" at 5507.12,5237.96 h60
  text "PTH" at 6143.67,5237.96 h60
  text "Slot" at 6402.78,5237.96 h60
  text "Top Layer - Bottom Layer" at 6777.93,5237.96 h60
  text "A" at 4849.24,5227.97 h55.19
  text "2" at 5175.11,5113.79 h60
  text "82.68mil (2.100mm)" at 5507.12,5113.79 h60
  text "PTH" at 6143.67,5113.79 h60
  text "Slot" at 6402.78,5113.79 h60
  text "Top Layer - Bottom Layer" at 6777.93,5113.79 h60
  text "1753 Total" at 5175.11,4989.61 h60
  text "Slot definitions :" at 4874.51,4902.69 h60
  text "Routed Path Length" at 5324.51,4902.69 h60
  text "= Calculated from tool start centre position to tool end centre position." at 5863.42,4902.69 h60
  text "Hole Length" at 5324.51,4853.02 h60
  text "= Routed Path Length + Tool Size = Slot length as defined in the PCB layout" at 5663.91,4853.02 h60
  text ".Layer_Name" at 577,-858.49 h60
M17 Embedded Cavity:
  text ".Layer_Name" at 577,-858.49 h60
M18 Embedded Assembly:
  text ".Layer_Name" at 577,-858.49 h60
M19 Embedded Keepout:
  text ".Layer_Name" at 577,-858.49 h60
DXF_PROC109E2_TASY:
  drawing of 6230 lines, arcs and shapes, not listed
DXF_PROC109E2_BASY:
  drawing of 6782 lines, arcs and shapes, not listed
  text "WHEN ACTUATOR IS OPENED" at -622.58,-301.75 h30 r270
  text "WHEN ACTUATOR IS OPENED" at -622.58,-301.75 h30 r270
LP Logo:
  drawing of 8965 lines, arcs and shapes, not listed
  text "4" at 6539.42,724 h30
  text "6" at 6676.42,724 h30
  text "4" at 6198.42,635 h30
  text "6" at 6068.42,634 h30
  text "6" at 6255.42,633 h30
  text "4" at 6010.42,631 h30
  text "6" at 412.42,629 h30
  text "4" at 360.42,626 h30
  text "2" at 985.42,595 h30
  text "20" at 1896.42,592 h30
  text "3" at 6581.42,592 h30
  text "20" at 4395.42,588 h30
  text "2" at 3492.42,587 h30
  text "6" at 6660.42,573 h30
  text "4" at 6555.42,571 h30
  text "6" at -206.58,550 h30
  text "J2" at 2005.42,504 h30
  text "J6" at 4503.42,503 h30
  text "4" at -207.58,490 h30
  text "3" at 6199.42,490 h30
  text "3" at 6007.42,488 h30
  text "3" at -54.58,482 h30
  text "3" at 356.42,461 h30
  text "3" at 6579.42,436 h30
  text "5" at 79.42,424 h30
  text "4" at 6005.42,421 h30
  text "4" at 429.42,419 h30
  text "3" at 5867.42,419 h30
  text "B" at -273.58,401 h30
  text "J4" at 2002.42,392 h30
  text "J8" at 4500.42,391 h30
  text "6" at 6003.42,369 h30
  text "5" at 489.51,350.88 h30
  text "40" at -334.58,347 h30
  text "6" at 167.92,345 h30
  text "NOT FCC APPROVED FOR RESALE" at 6690.44,345.25 h50 r90
  text "20" at -110.58,339 h30 r270
  text "16" at 276.42,336 h30 r270
  text "19" at 1905.42,315 h30
  text "19" at 4398.42,312 h30
  text "8" at 489.51,290.88 h30
  text "FOR EVALUATION ONLY;" at 6590.49,290.27 h50 r90
  text "5" at 770.42,273 h30
  text "13" at 275.42,270 h30 r270
  text "16" at -71.58,262 h30
  text "A" at 1207.42,260 h30
  text "10" at 180.42,259 h30
  text "B" at 1512.42,240 h30
  text "13" at 4353.42,240 h30
  text "10" at 3277.42,239 h30
  text "12" at 4019.42,238 h30
  text "12" at 353.42,224 h30
  text "9" at 428.42,217 h30
  text "3" at 2476.42,213 h30
  text "5" at 4356.42,192 h30
  text "15" at -6.58,178 h30
  text "11" at 102.42,177 h30
  text "3" at 926.42,159 h30
  text "4" at 737.42,158 h30
  text "3" at 4510.42,149 h30
  text "4" at 4359.92,146 h30
  text "5" at 3491.09,124.33 h30
  text "5" at 2323.42,109 h30
  text "6" at 3270.42,92 h30
  text "4" at 2473.42,78 h30
  text "A" at 260.42,38 h30
  text "97" at 207.42,-61 h30
  text "128" at 716.42,-61 h30
  text "24" at 4328.42,-81 h30
  text "6" at 4329.42,-151 h30
  text "5" at 4154.42,-155 h30
  text "16" at 5343.42,-157 h30
  text "5" at 4905.42,-191 h30
  text "4" at 4832.42,-193 h30
  text "3" at 5775.42,-206 h30
  text "4" at 5904.42,-216 h30
  text "WHEN ACTUATOR IS OPENED" at -616.5,-219 h30 r270
  text "4" at -222.58,-222 h30
  text "6" at 5904.42,-266 h30
  text "3" at 967.42,-273 h30
  text "4" at 1055.42,-276 h30
  text "3" at 5774.42,-316 h30
  text "4" at 5900.42,-328 h30
  text "TEST AUTOMATION" at -357.58,-338 h30 r270
  text "3" at -229.58,-344 h30
  text "3" at 4833.42,-382 h30
  text "6" at 5899.42,-386 h30
  text "5" at 1055.42,-398 h30
  text "2" at -100.58,-404 h30
  text "39" at 3575.42,-458 h30 r270
  text "42" at 3640.42,-458 h30 r270
  text "4" at 5907.42,-458 h30
  text "C" at 2396.42,-459 h30
  text "3" at 5765.42,-462 h30
  text "9" at 5333.09,-500.67 h30
  text "6" at 5904.42,-509 h30
  text "38" at 3524.42,-510 h30
  text "6" at -160.58,-512 h30
  text "8" at 5594.42,-543 h30
  text "6" at 4327.42,-579 h30
  text "5" at 4150.42,-580 h30
  text "3" at 5607.42,-588 h30
  text "4" at 5741.42,-589 h30
  text "4" at -174.58,-605 h30
  text "3" at -409.58,-627 h30
  text "6" at 5741.42,-643 h30
  text "4" at -250.58,-664 h30
  text "65" at 93.42,-668 h30
  text "32" at 816.42,-672 h30
  text "3" at 5608.42,-703 h30
  text "4" at 5742.42,-705 h30
  text "5" at -252.58,-744 h30
  text "6" at 5740.42,-756 h30
  text "64" at 206.42,-782 h30
  text "33" at 699.42,-786 h30
  text "4" at 75.42,-792 h30
  text "22" at 3529.42,-824 h30
  text "C" at 1211.42,-886 h30
  text "www.ti.com/launchpad" at 3329.42,-889 h30 r90
  text "21" at 3576.42,-902 h30 r270
  text "18" at 3643.42,-907 h30 r270
  text "3" at 25.42,-908 h30
  text "2" at 151.42,-911 h30
  text "5" at 4928.42,-953 h30
  text "8" at 1973.42,-962 h30
  text "4" at 4851.42,-962 h30
  text "16" at 827.42,-974 h30
  text "9" at 628.42,-977 h30
  text "4" at 5923.42,-994 h30
  text "5" at 1964.42,-1067 h30
  text "4" at 2072.42,-1083 h30
  text "2" at 980.42,-1104 h30
  text "20" at 4412.42,-1106 h30
  text "2" at 3482.42,-1107 h30
  text "20" at 1893.42,-1108 h30
  text "8" at 5775.42,-1126 h30
  text "Development Kit" at 3049.42,-1136 h30 r90
  text "LP-AM243" at 2998.42,-1138 h30 r90
  text "3" at 4851.42,-1156 h30
  text "5" at 5885.42,-1174 h30 r270
  text "J7" at 4501.42,-1192 h30
  text "J3" at 1997.42,-1194 h30
  text "7" at 4904.42,-1239 h30
  text "10" at 5140.42,-1241 h30
  text "J5" at 4498.42,-1304 h30
  text "J1" at 1994.42,-1306 h30
  text "8" at 623.42,-1315 h30
  text "2" at 4913.42,-1335 h30
  text "19" at 1872.42,-1387 h30
  text "19" at 4404.42,-1388 h30
  text "4" at 1864.42,-1476 h30
  text "3" at 2031.42,-1476 h30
